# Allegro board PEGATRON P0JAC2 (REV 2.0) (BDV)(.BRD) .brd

Outline 101.61 x 124.8 mm; copper layers: TOP, L2-SIG, L3-GND, L4-SIG, L5-SIG, L6-GND, L7-SIG, BOTTOM. Coordinates in mm from the lower left corner of the outline.

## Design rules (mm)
net group I2C: nets I2C_3_SCL I2C_3_SDA I2C_CAM2_SCL I2C_CAM2_SDA

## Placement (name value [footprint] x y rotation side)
C0706  -  [TX_C0402]  88.72 66.89 270 bottom
C0707  -  [TX_C0402]  87.99 66.89 270 bottom
C0708  -  [TX_C0402]  87.27 66.89 270 bottom
C0710  -  [TX_C0402]  86.94 63.41 180 bottom
C0713  -  [TX_C0402]  86.53 66.89 270 bottom
C0714  -  [TX_C0402]  90.69 87.49 180 bottom
C0715  -  [TX_C0402]  92.33 89.95 0 bottom
C0722  -  [TX_C0402]  85.6 61.5 90 bottom
C0787  -  [TX_C0402]  89.44 66.89 270 bottom
C0901  -  [TX_C0402]  89.02 35.85 0 bottom
C0902  -  [TX_C0402]  86.02 44.08 0 bottom
C0903  -  [TX_C0402]  86.02 44.84 0 bottom
C0904  -  [TX_C0402]  86.02 47.13 0 bottom
C0905  -  [TX_C0402]  86.02 47.89 0 bottom
C0906  -  [TX_C0402]  86.02 40.9 0 bottom
C0907  -  [TX_C0402]  86.02 41.67 0 bottom
C0908  -  [TX_C0402]  86.02 37.86 0 bottom
C0909  -  [TX_C0402]  86.02 38.62 0 bottom
C0910  -  [TX_C0402]  87.29 29.8 90 bottom
C0951  -  [TX_C0402]  85.39 32.09 180 bottom
C0952  -  [TX_C0402]  86.53 32.47 270 bottom
C1001  -  [TX_C0603]  22.09 64.6 180 bottom
C1002  -  [TX_C0402]  23.51 64.53 90 bottom
C1003  -  [TX_C0402_H24]  22.85 65.8 0 bottom
C1004  -  [TX_C0402_H24]  22.85 66.76 0 bottom
C1005  -  [TX_C0402_H24]  23.16 69.55 180 bottom
C1006  -  [TX_C0402_H24]  23.16 70.32 180 bottom
C1007  -  [TX_C0603]  22.03 62.4 180 bottom
C1008  -  [TX_C0603]  22.09 63.49 180 bottom
C1010  -  [TX_C0402]  34.66 68.92 270 bottom
C1020  -  [TX_C0402]  32.63 63.42 90 bottom
C1021  -  [TX_C0402]  33.22 65.46 90 bottom
C1022  -  [TX_C0402]  33.98 65.46 270 bottom
C1023  -  [TX_C0402]  32.48 67.62 270 bottom
C1024  -  [TX_C0402]  33.24 67.62 90 bottom
C1025  -  [TX_C0402]  28.14 60.03 180 bottom
C1026  -  [TX_C0402]  28.14 60.77 180 bottom
C1027  -  [TX_C0402]  22.78 68.41 270 bottom
C1028  -  [TX_C0603]  21.62 68.58 90 bottom
C1029  -  [TX_C0402]  31.58 61.43 0 bottom
C1030  -  [TX_C0603]  31.17 59.97 270 bottom
C1040  -  [TX_C0603]  24.18 61.66 180 bottom
C1044  -  [TX_C0402]  29.33 70.57 90 bottom
C1045  -  [TX_C0402]  28.58 70.57 90 bottom
C1046  -  [TX_C0402]  27.79 70.57 90 bottom
C1047  -  [TX_C0402]  27.03 70.57 90 bottom
C1052  -  [TX_C0402]  28.14 59.29 180 bottom
C1053  -  [TX_C0402]  20.57 62.82 270 bottom
C1060  -  [TX_C0402]  35.43 70.57 90 bottom
C1061  -  [TX_C0402]  33.9 70.57 90 bottom
C1062  -  [TX_C0402]  31.62 70.57 90 bottom
C1063  -  [TX_C0402]  27.84 72.17 90 bottom
C1102  -  [TX_C0402]  25.6 60.89 90 bottom
C1105  -  [TX_C0402]  27.03 60.89 270 bottom
C1106  -  [TX_C0603]  24.78 59.47 180 bottom
C1601  -  [TX_C0402]  72.6 98.41 90 bottom
C1602  -  [TX_C0402]  64.73 86.85 0 bottom
C1603  -  [TX_C0402]  73.36 99.93 90 bottom
C1604  -  [TX_C0402]  59.57 85.38 270 bottom
C1605  -  [TX_C0402]  54.26 86.22 90 bottom
C1606  -  [TX_C0402]  72.6 99.96 90 bottom
C1607  -  [TX_C0402]  49.77 86.49 0 bottom
C1608  -  [TX_C0402]  72.6 96.86 270 bottom
C1609  -  [TX_C0402]  70.49 86.82 0 bottom
C1614  -  [TX_C0402]  57.82 99.65 180 bottom
C1615  -  [TX_C0402]  57.82 98.08 180 bottom
C1616  -  [TX_C0402]  59.11 101.53 270 bottom
C1617  -  [TX_C0402]  68.63 86.85 0 bottom
C1618  -  [TX_C0402]  57.64 101.53 90 bottom
C1619  -  [TX_C0402]  69.35 101.53 270 bottom
C1622  -  [TX_C0402]  73.76 101.53 270 bottom
C1623  -  [TX_C0402]  40.03 97.14 180 bottom
C1624  -  [TX_C0402]  72.29 101.53 270 bottom
C1625  -  [TX_C0402]  40.03 97.9 180 bottom
C1701  -  [TX_C0402]  54.61 101.58 270 bottom
C1702  -  [TX_C0402]  56.85 101.58 270 bottom
C1703  -  [TX_C0402]  48.29 86.4 270 bottom
C1704  -  [TX_C0402]  43.52 101.58 90 bottom
C1705  -  [TX_C0402]  40.03 100.24 180 bottom
C1707  -  [TX_C0402]  40.55 101.58 90 bottom
C1709  -  [TX_C0402]  63.38 82.76 270 bottom
C1710  -  [TX_C0402]  41.28 101.58 90 bottom
C1711  -  [TX_C0402]  47.91 84.36 270 bottom
C1712  -  [TX_C0402]  47.07 84.36 270 bottom
C1713  -  [TX_C0402]  70.09 83.9 270 bottom
C1714  -  [TX_C0402]  60.97 84.95 90 bottom
C1715  -  [TX_C0402]  52.41 86.85 0 bottom
C1716  -  [TX_C0402]  66.3 84.89 90 bottom
C1717  -  [TX_C0402]  52.76 84.74 270 bottom
C1722  -  [TX_C0402]  71.55 101.53 270 bottom
C1723  -  [TX_C0402]  40.03 96.4 180 bottom
C1724  -  [TX_C0402]  40.03 98.64 180 bottom
C1725  -  [TX_C0402]  73.03 101.53 270 bottom
C1900  -  [TX_C0402]  30.96 82.72 270 bottom
C1902  -  [TX_C0402]  32.79 82.72 90 bottom
C1903  -  [TX_C0402]  21.21 88.02 180 bottom
C1904  -  [TX_C0402]  31.73 82.72 270 bottom
C1905  -  [TX_C0402]  21.18 91.85 180 bottom
C1909  -  [TX_C0402]  34.39 82.72 270 bottom
C1911  -  [TX_C0402]  29.41 82.72 270 bottom
C1912  -  [TX_C0402]  21.21 87.26 180 bottom
C1913  -  [TX_C0402]  21.21 88.76 180 bottom
C1914  -  [TX_C0402]  21.21 89.49 180 bottom
C1915  -  [TX_C0402]  21.18 91.09 180 bottom
C1916  -  [TX_C0402]  21.18 90.33 180 bottom
C2011  -  [TX_C0402]  95.83 92.77 0 bottom
C2036  -  [TX_C0402]  25.02 5.04 180 bottom
C2101  -  [TX_C0402]  11.35 111.77 90 bottom
C2102  -  [TX_C0402]  12.87 111.77 90 bottom
C2104  -  [TX_C0402]  15.01 111.26 90 bottom
C2122  -  [TX_C0402]  13.63 111.77 90 bottom
C2124  -  [TX_C0402]  74.35 95.72 180 bottom
C2125  -  [TX_C0402]  80.44 96.47 90 bottom
C2126  -  [TX_C0402]  74.35 98 0 bottom
C2127  -  [TX_C0402]  12.11 111.77 90 bottom
C2128  -  [TX_C0402]  15.75 111.26 90 bottom
C2301  -  [TX_C0402]  83.59 3.82 90 bottom
C2401  -  [TX_C0402]  53.59 81.34 90 bottom
C2600  -  [TX_C0402]  42.26 59.21 270 bottom
C2601  -  [TX_C0402]  42.26 60.73 90 bottom
C2602  -  [TX_C0402]  78.87 65.8 0 bottom
C2603  -  [TX_C0402]  78.87 63.59 0 bottom
C2604  -  [TX_C0402]  65.28 62.19 0 bottom
C2605  -  [TX_C0402]  65.28 61.4 180 bottom
C2606  -  [TX_C0402]  62.74 60.26 90 bottom
C2608  -  [TX_C0402]  65.6 66.48 270 bottom
C2610  -  [TX_C0201]  61.56 58.66 270 bottom
C2611  -  [TX_C0402]  65.25 69.02 0 bottom
C2612  -  [TX_C0402]  65.28 62.95 0 bottom
C2701  -  [TX_C0603_H37]  79.25 74.38 180 bottom
C2706  -  [TX_C0402]  43.13 68.41 180 bottom
C2707  -  [TX_C0402]  43.13 70.62 180 bottom
C2709  -  [TX_C0402]  54.61 61.05 0 bottom
C2710  -  [TX_C0402]  54.61 59.55 0 bottom
C2713  -  [TX_C0402]  54.61 60.28 0 bottom
C2717  -  [TX_C0402]  48.64 60.31 180 bottom
C2718  -  [TX_C0402_H24]  48.64 61.07 180 bottom
C2722  -  [TX_C0402]  51.69 61.07 180 bottom
C2723  -  [TX_C0402]  58.17 60.61 270 bottom
C2724  -  [TX_C0402]  64.87 66.48 270 bottom
C2727  -  [TX_C0402_H24]  63.74 64.45 0 bottom
C2728  -  [TX_C0402]  63.74 63.69 0 bottom
C2729  -  [TX_C0402]  43.13 69.89 180 bottom
C2730  -  [TX_C0402]  48.64 59.55 180 bottom
C2732  -  [TX_C0402]  51.69 60.31 180 bottom
C2733  -  [TX_C0402]  43.13 73.59 180 bottom
C2734  -  [TX_C0402_H26]  63.36 70.16 270 bottom
C2735  -  [TX_C0402]  64.11 70.16 270 bottom
C2736  -  [TX_C0402]  65.64 70.16 270 bottom
C2737  -  [TX_C0402]  64.88 70.16 270 bottom
C2747  -  [TX_C0402]  61.6 61.05 0 bottom
C2748  -  [TX_C0402]  61.6 60.31 0 bottom
C2752  -  [TX_C0402]  50.17 60.31 180 bottom
C2753  -  [TX_C0402]  59.32 60.99 0 bottom
C2754  -  [TX_C0402]  55.73 60.66 270 bottom
C2758  -  [TX_C0402]  60.45 60.64 270 bottom
C2759  -  [TX_C0402]  56.85 61.05 0 bottom
C2760  -  [TX_C0402]  56.85 60.31 0 bottom
C2761  -  [TX_C0402]  56.85 59.57 0 bottom
C2762  -  [TX_C0402]  41.51 67.58 270 bottom
C2763  -  [TX_C0402]  43.49 67.29 270 bottom
C2766  -  [TX_C0402]  64.11 71.69 270 bottom
C2767  -  [TX_C0402]  42.73 74.79 90 bottom
C2768  -  [TX_C0402]  63.36 71.69 270 bottom
C2771  -  [TX_C0402]  41.97 74.79 90 bottom
C2772  -  [TX_C0402]  43.49 74.79 90 bottom
C2773  -  [TX_C0402]  63.36 73.21 90 bottom
C2774  -  [TX_C0402]  63.74 62.95 0 bottom
C2776  -  [TX_C0402]  50.17 61.07 180 bottom
C2777  -  [TX_C0402]  59.32 60.23 0 bottom
C2800  -  [TX_C0402]  63.74 68.26 0 bottom
C2802  -  [TX_C0402]  63.74 69.02 0 bottom
C2803  -  [TX_C0402]  63.74 67.5 0 bottom
C2804  -  [TX_C0402]  63.74 65.97 0 bottom
C2806  -  [TX_C0402]  63.74 66.73 0 bottom
C2807  -  [TX_C0402]  63.74 65.21 0 bottom
C2808  -  [TX_C0402]  44.58 59.65 270 bottom
C2809  -  [TX_C0402]  45.3 59.65 270 bottom
C2810  -  [TX_C0402]  43.1 64.73 180 bottom
C2811  -  [TX_C0402]  43.1 65.47 180 bottom
C2814  -  [TX_C0402]  43.1 63.26 180 bottom
C2815  -  [TX_C0402]  43.1 63.99 180 bottom
C2816  -  [TX_C0402_H26]  50.35 81.34 90 bottom
C2817  -  [TX_C0402]  51.24 81.34 90 bottom
C2818  -  [TX_C0402]  52.13 81.34 90 bottom
C2819  -  [TX_C0402]  58.1 81.34 90 bottom
C2820  -  [TX_C0402]  57.35 81.34 90 bottom
C2821  -  [TX_C0402]  56.63 81.34 90 bottom
C2822  -  [TX_C0402]  59.11 81.34 90 bottom
C2823  -  [TX_C0402]  48.88 81.34 90 bottom
C2824  -  [TX_C0402]  47.99 81.34 90 bottom
C2825  -  [TX_C0402]  43.13 72.86 180 bottom
C3001  -  [TX_C0402]  78.82 68.95 0 bottom
C3002  -  [TX_C0402]  69.93 62.54 90 bottom
C3003  -  [TX_C0201]  70.56 62.54 90 bottom
C3004  -  [TX_C0201]  74.55 62.85 0 bottom
C3005  -  [TX_C0201]  76.07 74.03 0 bottom
C3006  -  [TX_C0201]  73.51 62.85 180 bottom
C3007  -  [TX_C0201]  71.12 74.48 90 bottom
C3008  -  [TX_C0201]  66.52 68.18 180 bottom
C3009  -  [TX_C0201]  78.25 67.26 90 bottom
C3010  -  [TX_C0201]  67.29 68.27 90 bottom
C3011  -  [TX_C0201]  78.49 66.42 0 bottom
C3101  -  [TX_C0402]  40.01 99.45 180 bottom
C3311  -  [TX_C0402]  16.59 74.72 0 bottom
C3316  -  [TX_C0402]  80.65 90.36 270 bottom
C3317  -  [TX_C0402]  79.76 86.37 90 bottom
C3318  -  [TX_C0402]  79.4 80.78 90 bottom
C3319  -  [TX_C0402]  76.96 77.99 90 bottom
C3801  -  [TX_C0402]  84.23 89.06 180 bottom
C5101  -  [TX_C0402]  31.06 9.46 0 bottom
C5102  -  [TX_C0402]  25.4 10.75 270 bottom
C5103  -  [TX_C0402]  24.66 10.75 270 bottom
C5209  -  [TX_C0402]  72.16 48.9 180 bottom
C5210  -  [TX_C0402_H28]  73.2 46.87 270 bottom
C5211  -  [TX_C0402_H26]  89.35 59.01 90 bottom
C5212  -  [TX_C0402_H26]  89.35 57.49 270 bottom
C5214  -  [TX_C0402_H28]  73.94 46.87 270 bottom
C5215  -  [TX_C0402]  73.81 53.53 0 bottom
C5216  -  [TX_C0402]  89.35 55.91 90 bottom
C5217  -  [TX_C0402]  88.61 55.91 90 bottom
C5401  -  [TX_C0402_H26]  16.79 90.89 0 bottom
C5402  -  [TX_C0402]  16.79 90.08 0 bottom
C5403  -  [TX_C0402]  16.79 89.27 0 bottom
C5404  -  [TX_C0402]  1.88 81.01 90 bottom
C5405  -  [TX_C0402]  2.36 91.32 180 bottom
C5406  -  [TX_C0402_H26]  2.36 89.72 180 bottom
C5407  -  [TX_C0402]  2.36 88.12 0 bottom
C5410  -  [TX_C0402]  1.91 85.86 90 bottom
C5411  -  [TX_C0402]  17.15 77.48 0 bottom
C5412  -  [TX_C0402]  2.36 90.51 180 bottom
C5413  -  [TX_C0402]  2.36 92.14 180 bottom
C5414  -  [TX_C0402]  8.71 72.35 180 bottom
C5415  -  [TX_C0402]  8.77 74.26 270 bottom
C5416  -  [TX_C0402]  8.03 74.26 270 bottom
C5417  -  [TX_C0402]  5.78 74.26 270 bottom
C5810  -  [TX_C0402]  28.65 101.38 180 bottom
C5811  -  [TX_C0402]  28.68 99.35 180 bottom
C5812  -  [TX_C0402]  28.68 97.88 180 bottom
C5813  -  [TX_C0402]  88.57 111.77 90 bottom
C5819  -  [TX_C0402]  71.74 114.63 0 bottom
C5820  -  [TX_C0402]  69.55 113.57 270 bottom
C5841  -  [TX_C0402]  89.31 111.77 90 bottom
C5866  -  [TX_C0402]  89.31 108.52 270 bottom
C5867  -  [TX_C0402]  88.57 108.52 270 bottom
C5878  -  [TX_C0402]  92.51 67.24 0 bottom
C7001  -  [TX_C0402]  28.85 50.35 90 bottom
C7002  -  [TX_C0402]  34.39 49.08 90 bottom
C7003  -  [TX_C0402]  29.61 50.35 90 bottom
C7010  -  [TX_C0402]  37.36 47.41 90 bottom
C7011  -  [TX_C0402]  37.36 45.86 270 bottom
C7103  -  [TX_C0402_H26]  76.7 20.41 270 bottom
C7104  -  [TX_C0402]  64.43 20 90 bottom
C7105  -  [TX_C0402]  64.43 18.47 270 bottom
C7106  -  [TX_C0402]  72.18 22.95 0 bottom
C7108  -  [TX_C0402]  72 13.14 0 bottom
C7109  -  [TX_C0402]  67.43 13.14 0 bottom
C7110  -  [TX_C0402]  74.86 19.74 90 bottom
C7111  -  [TX_C0402]  65.17 16.19 180 bottom
C7112  -  [TX_C0402]  74.14 19.74 90 bottom
C7117  -  [TX_C0402]  54.17 19.57 90 bottom
C7118  -  [TX_C0402]  54.96 19.57 90 bottom
C7119  -  [TX_C0402_H24]  53.44 19.57 270 bottom
C7120  -  [TX_C0402]  52.65 19.57 270 bottom
C7125  -  [TX_C0402]  65 25.71 270 bottom
C7126  -  [TX_C0603_H39]  67.03 29.09 180 bottom
C7146  -  [TX_C0402]  69.43 23.41 90 bottom
C7147  -  [TX_C0402]  67.22 23.41 90 bottom
C7148  -  [TX_C0402]  67.95 23.41 90 bottom
C7149  -  [TX_C0402]  68.69 23.41 90 bottom
C7150  -  [TX_C0402]  41.17 24.47 180 bottom
C7166  -  [TX_C0402]  70.48 13.14 180 bottom
C7187  -  [TX_C0402]  68.95 13.14 0 bottom
C7312  -  [TX_C0402]  47.85 4.02 90 bottom
C7313  -  [TX_C0402]  47.98 9.11 90 bottom
C7316  -  [TX_C0603_H37]  55.25 13.42 0 bottom
C7317  -  [TX_C0402_H24]  53.29 12.48 180 bottom
C7318  -  [TX_C0402_H24]  47.22 9.11 90 bottom
C7321  -  [TX_C0402]  67.22 4.15 0 bottom
C7322  -  [TX_C0402]  67.22 3.37 0 bottom
C7323  -  [TX_C0402]  67.49 5.65 0 bottom
C7324  -  [TX_C0402]  67.22 4.92 0 bottom
C7330  -  [TX_C0402]  88.32 7.17 270 bottom
C7331  -  [TX_C0402]  87.61 5.83 0 bottom
C7341  -  [TX_C0402]  62.99 4.53 90 bottom
C7342  -  [TX_C0402]  62.99 3.01 270 bottom
C7350  -  [TX_C0402]  87.47 14.11 90 bottom
C7351  -  [TX_C0402]  88.24 14.11 90 bottom
C7352  -  [TX_C0402]  86.71 14.11 90 bottom
C7353  -  [TX_C0402]  87.37 11.01 90 bottom
C7354  -  [TX_C0402]  88.13 11.01 90 bottom
C7355  -  [TX_C0402]  86.61 11.01 90 bottom
C7356  -  [TX_C0402]  49.98 13.12 270 bottom
C7357  -  [TX_C0402]  49.22 13.12 270 bottom
C7358  -  [TX_C0402_H24]  50.74 13.12 90 bottom
C7359  -  [TX_C0402]  43.28 15.23 180 bottom
C7364  -  [TX_C0402]  54.97 12.48 0 bottom
C7377  -  [TX_C0402]  62.69 9.12 90 bottom
C7385  -  [TX_C0603]  52.99 13.42 180 bottom
C7388  -  [TX_C0402]  84.15 5.83 0 bottom
C7389  -  [TX_C0402]  84.56 7.22 270 bottom
C7390  -  [TX_C0402]  79.02 9.11 90 bottom
C7391  -  [TX_C0402]  78.84 5.83 180 bottom
C8001  -  [TX_C0402_H24]  73.36 9.5 0 bottom
C8002  -  [TX_C0402]  71.91 9.11 90 bottom
C8003  -  [TX_C0402]  68.71 6.77 0 bottom
C8004  -  [TX_C0402]  71.15 9.11 90 bottom
C8005  -  [TX_C0402]  73.36 8.77 0 bottom
C8100  -  [TX_C0402]  74.55 44.54 90 bottom
C8101  -  [TX_C0603_H39]  73.78 36.1 270 bottom
C8102  -  [TX_C0402]  80.93 43.9 270 bottom
C8105  -  [TX_C0603_H39]  75.26 46.57 270 bottom
C8106  -  [TX_C0402]  73.62 42.71 180 bottom
C8107  -  [TX_C0402]  80.19 43.9 270 bottom
C8108  -  [TX_C0603_H39]  76.38 46.57 270 bottom
C8109  -  [TX_C0603_H37]  29.9 43.82 180 bottom
C8110  -  [TX_C0402]  34.82 42.68 0 bottom
C8111  -  [TX_C0603_H39]  34.92 45.27 90 bottom
C8112  -  [TX_C0603_H39]  33.76 45.3 90 bottom
C8113  -  [TX_C0402]  36.24 45.45 0 bottom
C8114  -  [TX_C0402]  29.59 42.91 180 bottom
C8115  -  [TX_C0402]  80.04 84.2 0 bottom
C8116  -  [TX_C0402]  74.47 83.8 270 bottom
C8201  -  [TX_C0603]  52.97 37.83 270 bottom
C8202  -  [TX_C0603]  58.61 39.51 0 bottom
C8203  -  [TX_C0603]  51.87 37.83 270 bottom
C8204  -  [TX_C0603]  56.5 41.12 0 bottom
C8205  -  [TX_C0603]  56.5 40.02 0 bottom
C8206  -  [TX_C0603]  63.58 37.63 270 bottom
C8207  -  [TX_C0603]  64.69 37.63 270 bottom
C8208  -  [TX_C0603]  61.37 39.81 0 bottom
C8209  -  [TX_C0603]  61.37 40.9 0 bottom
C8210  -  [TX_C0603]  63.91 35.39 90 bottom
C8211  -  [TX_C0603_H39]  61.7 49.03 180 bottom
C8212  -  [TX_C0603_H39]  61.7 50.15 180 bottom
C8213  -  [TX_C0603_H39]  65.4 51.55 90 bottom
C8214  -  [TX_C0603_H39]  69.44 45.83 0 bottom
C8215  -  [TX_C0603_H39]  69.44 50.3 0 bottom
C8216  -  [TX_C0603_H39]  69.44 48.07 0 bottom
C8217  -  [TX_C0603_H39]  69.79 36.76 0 bottom
C8218  -  [TX_C0603_H39]  69.79 39.01 0 bottom
C8219  -  [TX_C0201]  65.28 42.96 180 bottom
C8220  -  [TX_C0603_H39]  59.51 46.83 0 bottom
C8221  -  [TX_C0603_H39]  59.51 47.94 0 bottom
C8222  -  [TX_C0603_H39]  52.91 52.02 90 bottom
C8223  -  [TX_C0603_H39]  49.38 52.02 90 bottom
C8224  -  [TX_C0603_H39]  48.51 48.09 180 bottom
C8225  -  [TX_C0603_H39]  48.51 49.23 180 bottom
C8226  -  [TX_C0603_H39]  48.51 45.87 180 bottom
C8227  -  [TX_C0603_H39]  48.51 46.97 180 bottom
C8228  -  [TX_C0201]  47.16 49.32 90 bottom
C8229  -  [TX_C0603]  63.42 32.65 270 bottom
C8230  -  [TX_C0603_H39]  71.01 29.57 270 bottom
C8231  -  [TX_C0603_H39]  69.87 29.57 270 bottom
C8232  -  [TX_C0603_H39]  68.73 29.57 270 bottom
C8233  -  [TX_C0603_H39]  72.16 29.57 270 bottom
C8235  -  [TX_C0603]  64.54 32.65 270 bottom
C8237  -  [TX_C0603_H39]  71.42 33.29 0 bottom
C8239  -  [TX_C0603]  56.36 30.26 180 bottom
C8241  -  [TX_C0603_H39]  51.17 27.39 180 bottom
C8242  -  [TX_C0603_H39]  51.18 26.25 180 bottom
C8244  -  [TX_C0603_H39]  51.18 25.08 180 bottom
C8245  -  [TX_C0603_H39]  51.18 23.96 180 bottom
C8246  -  [TX_C0603]  53.09 35.54 90 bottom
C8248  -  [TX_C0603_H39]  46.48 34.57 180 bottom
C8249  -  [TX_C0603_H39]  46.48 35.67 180 bottom
C8250  -  [TX_C0603_H39]  47.42 37.3 90 bottom
C8251  -  [TX_C0603]  52.91 32.06 270 bottom
C8253  -  [TX_C0603_H39]  46.53 29.8 90 bottom
C8254  -  [TX_C0603_H39]  47.64 29.8 90 bottom
C8255  -  [TX_C0603_H39]  45.41 27.64 270 bottom
C8256  -  [TX_C0603_H39]  47.64 27.64 270 bottom
C8257  -  [TX_C0603_H39]  49.4 27.01 270 bottom
C8258  -  [TX_C0603]  65.28 27.75 270 bottom
C8260  -  [TX_C0603_H37]  61.06 23.94 180 bottom
C8261  -  [TX_C0603_H37]  61.36 26.15 180 bottom
C8262  -  [TX_C0603_H37]  62.38 22.16 0 bottom
C8263  -  [TX_C0603_H37]  61.36 27.29 180 bottom
C8264  -  [TX_C0603_H37]  61.36 28.43 180 bottom
C8265  -  [TX_C0603_H37]  61.06 25.04 180 bottom
C8266  -  [TX_C0402]  62.88 51.06 180 bottom
C8267  -  [TX_C0402]  62.88 51.83 180 bottom
C8268  -  [TX_C0402]  65.96 53.02 180 bottom
C8269  -  [TX_C0402]  54.81 52 90 bottom
C8270  -  [TX_C0402]  55.6 52 90 bottom
C8271  -  [TX_C0402]  62.61 53.22 0 bottom
C8273  -  [TX_C0603_H39]  71.42 34.41 0 bottom
C8274  -  [TX_C0603_H39]  61.7 46.8 180 bottom
C8275  -  [TX_C0603_H39]  61.7 47.91 180 bottom
C8276  -  [TX_C0603_H39]  69.44 44.71 0 bottom
C8277  -  [TX_C0603_H39]  64.26 51.55 90 bottom
C8278  -  [TX_C0603_H39]  69.44 46.95 0 bottom
C8279  -  [TX_C0603_H39]  69.44 49.18 0 bottom
C8280  -  [TX_C0603_H39]  69.79 35.66 0 bottom
C8281  -  [TX_C0603_H39]  69.79 37.88 0 bottom
C8282  -  [TX_C0603_H39]  59.51 49.04 0 bottom
C8283  -  [TX_C0603_H39]  59.53 50.16 0 bottom
C8284  -  [TX_C0603_H39]  50.5 52.02 90 bottom
C8285  -  [TX_C0603_H39]  51.61 52.02 90 bottom
C8286  -  [TX_C0603_H39]  48.25 52.02 90 bottom
C8287  -  [TX_C0603_H39]  48.51 50.38 180 bottom
C8288  -  [TX_C0603_H39]  48.51 43.65 180 bottom
C8289  -  [TX_C0603_H39]  48.51 44.76 180 bottom
C8290  -  [TX_C0402]  50.03 20.02 180 bottom
C8291  -  [TX_C0402]  48.63 19.64 90 bottom
C8299  -  [TX_C0402]  71.27 35.85 270 bottom
C8301  -  [TX_C0201]  49.3 33.08 180 bottom
C8302  -  [TX_C0603_H39]  46.98 32.6 90 bottom
C8303  -  [TX_C0603_H39]  48.13 32.6 90 bottom
C8304  -  [TX_C0603_H37]  69.62 40.78 270 bottom
C8305  -  [TX_C0603_H37]  59.39 24.95 270 bottom
C8306  -  [TX_C0201]  42.11 38.11 90 bottom
C8307  -  [TX_C0603]  71.85 25.85 90 bottom
C8308  -  [TX_C0402]  70.94 25.54 90 bottom
C8309  -  [TX_C0402]  71.75 27.29 0 bottom
C8310  -  [TX_C0201_H14]  43.59 40.55 90 bottom
C8311  -  [TX_C0603_H37]  47.01 41.21 270 bottom
C8312  -  [TX_C0603_H37]  45.71 41.18 270 bottom
C8313  -  [TX_C0603_H37]  44.47 41.21 270 bottom
C8314  -  [TX_C0402]  47.09 39.79 0 bottom
C8315  -  [TX_C0402_H26]  44.83 38.01 180 bottom
C8316  -  [TX_C0201_H14]  48.55 36.56 180 bottom
C8317  -  [TX_C0402]  43.63 37.55 270 bottom
C8318  -  [TX_C0603_H37]  43.2 44.15 270 bottom
C8319  -  [TX_C0402_H24]  51.77 33.46 270 bottom
C8320  -  [TX_C0603_H39]  57.68 23.2 0 bottom
C8321  -  [TX_C0603_H39]  57.68 24.32 0 bottom
C8322  -  [TX_C0603_H39]  54.35 25.51 180 bottom
C8323  -  [TX_C0603_H39]  57.68 22.08 0 bottom
C8324  -  [TX_C0603_H39]  54.35 23.22 180 bottom
C8325  -  [TX_C0603_H39]  54.35 24.37 180 bottom
C8326  -  [TX_C0603_H39]  57.68 25.43 0 bottom
C8327  -  [TX_C0603]  59.94 29.58 180 bottom
C8329  -  [TX_C0402]  58.31 19.57 90 bottom
C8330  -  [TX_C0402]  64.97 23.3 270 bottom
C8331  -  [TX_C0402_H26]  74.67 24.9 270 bottom
C8332  -  [TX_C0402]  77.12 28.71 0 bottom
C8333  -  [TX_C0402]  78.84 27.62 0 bottom
C8334  -  [TX_C0402]  80.41 25.31 0 bottom
C8335  -  [TX_C0402]  36.58 65.47 90 bottom
C8336  -  [TX_C0402]  34.27 60.56 90 bottom
C8341  -  [TX_C0402]  74.14 29.78 180 bottom
C8342  -  [TX_C0201_H14]  64.19 30.79 270 bottom
C8343  -  [TX_C0402]  73.67 34.09 270 bottom
C8344  -  [TX_C0201]  76.78 32.32 270 bottom
C8345  -  [TX_C0402]  73.71 32.55 270 bottom
C8346  -  [TX_C0201]  74.65 31.15 90 bottom
C8348  -  [TX_C0402]  56.84 18.02 270 bottom
C8349  -  [TX_C0402]  80.82 23.73 90 bottom
C8367  -  [TX_C0402]  55.83 25.36 90 bottom
C8401  -  [TX_C0201_H14]  58.14 20.94 270 bottom
C8402  -  [TX_C0402]  49.3 23.22 90 bottom
C8405  -  [TX_C0402]  37.11 41.89 90 bottom
C8406  -  [TX_C0402]  43.19 42 90 bottom
C8407  -  [TX_C0402]  30.46 51.95 180 bottom
C8408  -  [TX_C0402]  35.68 50.76 270 bottom
C8409  -  [TX_C0201_H14]  63.63 30.79 270 bottom
C8410  -  [TX_C0201]  59.77 20.94 270 bottom
C8411  -  [TX_C0201]  41.58 38.11 90 bottom
C8412  -  [TX_C0402]  36.57 50.63 270 bottom
C8800  -  [TX_C0402_H26]  38.86 23 180 bottom
C8801  -  [TX_C0805]  38.75 21.14 270 bottom
C8802  -  [TX_C0402]  38.07 25.13 180 bottom
C8803  -  [TX_C0402]  37.05 21.09 0 bottom
C8804  -  [TX_C0805]  36.46 19.92 180 bottom
C8805  -  [TX_C0805]  36.46 18.27 180 bottom
C8806  -  [TX_C0402]  37.05 21.83 0 bottom
C8807  -  [TX_C0402]  38.91 36.23 0 bottom
C8808  -  [TX_C0402]  38.91 35.49 0 bottom
C8809  -  [TX_C0603_H39]  39.11 34.53 0 bottom
C8810  -  [TX_C0603_H39]  39.11 33.38 0 bottom
C8811  -  [TX_C0402]  30.93 26.02 180 bottom
C8812  -  [TX_C0603_H37]  31.16 26.93 180 bottom
C8814  -  [TX_C0603]  69.06 9.33 0 bottom
C8816  -  [TX_C0402]  31.69 13.27 270 bottom
C8817  -  [TX_C0402]  30.56 13.62 0 bottom
C8818  -  [TX_C0402]  31.24 16.93 180 bottom
C8905  -  [TX_C0402]  29.63 31.4 90 bottom
C8906  -  [TX_C0402]  25.32 40.22 270 bottom
C8907  -  [TX_C0402]  30.02 32.51 180 bottom
C8911  -  [TX_C0402]  25.73 44.28 90 bottom
C8912  -  [TX_C0402]  30.02 33.23 180 bottom
C8913  -  [TX_C0402]  30.03 35.42 180 bottom
C8916  -  [TX_C0402]  34.44 35.81 90 bottom
C8917  -  [TX_C0402]  33.29 37.07 0 bottom
C8918  -  [TX_C0402]  33.29 37.86 0 bottom
C8919  -  [TX_C0402]  34.82 37.45 180 bottom
C9000  -  [TX_C0402]  40.24 14.23 0 bottom
C9001  -  [TX_C0402_H24]  40.24 14.97 0 bottom
C9002  -  [TX_C0402]  42.72 21.5 180 bottom
C9003  -  [TX_C0402]  41.17 23.73 0 bottom
C9004  -  [TX_C0402_H24]  43.71 18.12 270 bottom
C9005  -  [TX_C0805_H49]  43.66 4.99 0 bottom
C9006  -  [TX_C0603_H37]  47.18 5.34 0 bottom
C9007  -  [TX_C0402]  41.17 25.94 180 bottom
C9008  -  [TX_C0402]  42.85 27.26 90 bottom
C9009  -  [TX_C0603_H37]  46.91 18.07 270 bottom
C9010  -  [TX_C0805_H49]  43.66 3.34 0 bottom
CE5201  -  [TX_C3216_H47]  88.77 51.7 90 bottom
CE5202  -  [TX_C3216_H47]  86.86 51.7 90 bottom
CE8100  -  [TX_C3216_H47]  77.85 49.39 270 bottom
CE8101  -  [TX_C3216_H47]  79.73 48.19 270 bottom
CE8102  -  [TX_C3528_SANYO_H47]  31.85 40.06 180 bottom
CON0700  -  [TX_MICRO_SD_8P_11HOLD]  93.63 75.56 270 bottom
CON0901  -  [T_NB_HDMI_19P_16_4HL_RA_LF2]  97.13 40.24 90 top
CON1102  -  [TX_WTOB_4P_31_2H_ENT]  34.37 2.36 180 bottom
CON2002  -  [TX_FPC_18P_20_2H_RA_B]  1.65 64.6 90 bottom
CON2003  -  [TX_FPC_6P_20_2HOLD_ACES]  20.55 3.03 180 bottom
CON2101  -  [TX_FPC_21P_24_2H_RA_SUNG]  6.55 119.79 180 bottom
CON3301  -  [TX_FPC_12P_20_2HOLD_RA_PTWO]  13.87 70.95 180 bottom
CON3800  -  [TX_BTOB_60P_16_4H_F_PANA]  86.6 92.87 270 bottom
CON5101  -  [TX_WTOB_9P_79_2HOLD_ACE]  18.98 24.5 90 bottom
CON5201  -  [TX_USB_5P_4HOLD_RA_ACON]  97.76 56.97 90 top
CON7305  -  [TX_FPC_39P_24_2HOLD_RA_HSR]  55.36 3.32 180 bottom
CON8001  -  [TX_WTOB_4P_49_2HOLD_RA_H88]  73.51 1.9 180 bottom
CON8902  -  [TX_WTOB_6P_79_2HOLD_ACE]  18.98 47.15 90 bottom
D0700  -  [TX_ESD_2P_33_39X24_H20]  90.73 85.05 180 bottom
D0701  -  [TX_ESD_2P_33_39X24_H20]  90.73 84.21 180 bottom
D0702  -  [TX_ESD_2P_33_39X24_H20]  90.68 89.11 180 bottom
D0703  -  [TX_ESD_2P_33_39X24_H20]  90.68 88.27 180 bottom
D0704  -  [TX_ESD_2P_33_39X24_H20]  90.73 85.89 180 bottom
D0705  -  [TX_ESD_2P_33_39X24_H20]  90.7 86.7 180 bottom
D0706  -  [TX_ESD_2P_33_39X24_H20]  90.68 89.95 180 bottom
D0905  -  [TX_SOT323]  85.85 34.76 270 bottom
D1101  -  [TX_ESD_2P_33_39X24_H20]  32.41 5.66 180 bottom
D1102  -  [TX_ESD_2P_33_39X24_H20]  34.04 5.66 0 bottom
D1103  -  [TX_ESD_2P_33_39X24_H20]  35.65 5.65 180 bottom
D1104  -  [TX_ESD_2P_33_39X24_H20]  37.28 5.65 0 bottom
D2003  -  [TX_DIODE_2P_39X24_INFINEON]  96.27 95.29 90 bottom
D2701  -  [TX_SOT323]  79.17 72.3 270 bottom
D5102  -  [TX_SOT323]  25.93 8.82 180 bottom
D5103  -  [TX_DIODE_2P_39X24_INFINEON]  29.77 17.05 0 bottom
D5104  -  [TX_SOT323]  28.91 2.68 180 bottom
D8101  -  [TX_SOT323]  71.65 46.97 90 bottom
D8201  -  [TX_DFN1006_2]  62.81 30.92 270 bottom
D9000  -  [TX_POWERDI123]  42.36 18.3 90 bottom
D9001  -  [TX_POWERDI123]  45.74 7.04 180 bottom
F0921  -  [TX_FUSE_2P_39X20_H14]  87.98 36.6 0 bottom
H7901  -  [HOLE_O118X106DO118X106N]  95.11 101.25 90 top
H7903  -  [HOLE_C106D106N]  92.51 48.5 0 top
H7906  -  [HOLE_C106D106N]  14.09 121.95 0 top
H7907  -  [HOLE_CRT262X204D79]  93.6 32.74 0 top
H7910  -  [HH_H_RC262X258D79N_P2_V4]  14.09 117.45 0 top
H7911  -  [HH_H_R276X277D79N_M2_P2_V4]  95.1 106.4 0 top
J3101  -  [TX_FPC_CON_34P_31_2HD_T]  63.29 108.67 180 top
JP1601  -  [2MM_OPEN_5MIL_M1M2]  44.22 83.27 180 bottom
JP1602  -  [1MM_OPEN_5MIL_M1M2]  44.32 33.66 180 bottom
JP8100  -  [HH_PWR_FB_SHORT_PT]  79.78 47.58 90 bottom
JP8101  -  [1MM_OPEN_5MIL_M1M2]  72.88 39.07 90 bottom
JP8102  -  [1MM_OPEN_5MIL_M1M2]  74.96 48.7 270 bottom
JP8201  -  [HH_PWR_FB_SHORT_PT]  72.16 29.85 270 bottom
JP8202  -  [HH_PWR_FB_SHORT_PT]  71.09 34.45 0 bottom
JP8203  -  [HH_PWR_FB_SHORT_PT]  51.43 23.96 180 bottom
JP8204  -  [HH_PWR_FB_SHORT_PT]  46.64 34.53 0 bottom
JP8205  -  [HH_PWR_FB_SHORT_PT]  46.53 29.63 270 bottom
JP8206  -  [HH_PWR_FB_SHORT_PT]  62.1 22.26 180 bottom
JP8207  -  [HH_PWR_FB_SHORT_PT]  70.1 50.86 270 bottom
JP8301  -  [HH_PWR_FB_SHORT_PT]  46.98 31.45 270 bottom
JP8302  -  [HH_PWR_FB_SHORT_PT]  57.04 21.5 90 bottom
JP8303  -  [HH_PWR_FB_SHORT_PT]  73.53 25.41 180 bottom
JP8304  -  [HH_PWR_FB_SHORT_PT]  80.08 24.98 270 bottom
JP8305  -  [HH_PWR_FB_SHORT_PT]  36.98 65.06 0 bottom
JP8306  -  [1MM_OPEN_5MIL_M1M2]  38.68 73.72 180 bottom
JP8307  -  [1MM_OPEN_5MIL_M1M2]  40.54 73.72 180 bottom
JP8402  -  [HH_PWR_FB_SHORT_PT]  37.14 41.08 270 bottom
JP8800  -  [2MM_OPEN_5MIL_M1M2]  31.01 29.07 180 bottom
JP8900  -  [HH_PWR_FB_SHORT_PT]  29.59 48.45 90 bottom
JP8901  -  [HH_PWR_FB_SHORT_PT]  28.7 47.69 270 bottom
JP9000  -  [1MM_OPEN_5MIL_M1M2]  46.5 2.96 90 bottom
JP9001  -  [HH_PWR_FB_SHORT_PT]  46.88 5.32 180 bottom
L0900  -  [TX_CHOKE_4P_49X39]  87.92 44.46 0 bottom
L0901  -  [TX_CHOKE_4P_49X39]  87.92 47.51 0 bottom
L0902  -  [TX_CHOKE_4P_49X39]  87.92 41.31 0 bottom
L0903  -  [TX_CHOKE_4P_49X39]  87.92 38.21 0 bottom
L2102  -  [TX_CHOKE_4P_49X39]  22.57 98.36 90 bottom
L2104  -  [TX_CHOKE_4P_49X39]  21.36 98.36 90 bottom
L3001  -  [TX_L0402_H24]  68.3 62.26 0 bottom
L3002  -  [TX_L0402_H24]  68.3 62.97 0 bottom
L3003  -  [TX_L0402_H24]  70.05 74.11 180 bottom
L5201  -  [TX_CHOKE_4P_49X39]  87.88 58.25 180 bottom
L5202  -  [TX_L0805_H43]  86.34 55.58 0 bottom
L7102  -  [TX_L0603_H26]  75.77 20.05 270 bottom
L7111  -  [TX_L1008_MURA]  75.05 22.56 0 bottom
L7303  -  [TX_L0402_H24]  52.5 14.41 0 bottom
L7304  -  [TX_L0402_H24]  45.69 9.11 270 bottom
L7305  -  [TX_L0402_H24]  46.45 9.11 270 bottom
L7306  -  [TX_L0402_H24]  65.33 8.95 180 bottom
L7350  -  [TX_L0402_H24]  63.81 8.95 180 bottom
L8001  -  [TX_L0805_H43]  69.34 7.97 180 bottom
L8100  -  [TX_INDUCTOR_2P_213X205_H59]  77.48 38.06 0 bottom
L8101  -  [TX_INDUCTOR_2P_98X79_TAIYO]  31.7 45.63 0 bottom
L8201  -  [TX_INDUCTOR_2P_98X79_TAIYO]  62.54 43.27 270 bottom
L8202  -  [TX_INDUCTOR_2P_98X79_TAIYO]  60.25 43.27 270 bottom
L8203  -  [TX_INDUCTOR_2P_98X79_TAIYO]  66 40.99 180 bottom
L8204  -  [TX_INDUCTOR_2P_98X79_TAIYO]  66.92 38.74 180 bottom
L8205  -  [TX_INDUCTOR_2P_98X79_TAIYO]  66.82 36.27 180 bottom
L8206  -  [TX_INDUCTOR_2P_98X79_TAIYO]  55.73 43.24 270 bottom
L8207  -  [TX_INDUCTOR_2P_98X79_TAIYO]  58.01 43.24 270 bottom
L8208  -  [TX_INDUCTOR_2P_98X79_TAIYO]  52.86 43.24 270 bottom
L8209  -  [TX_INDUCTOR_2P_98X79_TAIYO]  51 40.27 0 bottom
L8210  -  [TX_INDUCTOR_2P_98X79_TAIYO]  49.78 37.96 0 bottom
L8211  -  [TX_INDUCTOR_2P_98X79_TAIYO]  67.11 31.79 180 bottom
L8212  -  [TX_INDUCTOR_2P_98X79_TAIYO]  67.13 34.03 180 bottom
L8213  -  [TX_INDUCTOR_2P_98X79_TAIYO]  55.17 27.85 0 bottom
L8214  -  [TX_INDUCTOR_2P_98X79_TAIYO]  50.57 35.42 180 bottom
L8215  -  [TX_INDUCTOR_2P_98X79_TAIYO]  50.75 31.58 180 bottom
L8216  -  [TX_INDUCTOR_2P_98X79_TAIYO]  63.6 28.18 270 bottom
L8301  -  [TX_INDUCTOR_2P_98X79_TAIYO]  58.8 27.82 180 bottom
L8801  -  [TX_INDUCTOR_2P_213X205_H59]  36.57 30.03 180 bottom
L9000  -  [TX_L1008_TAIYO_H47]  45.18 20 90 bottom
LX7324  -  [TX_CHOKE_4P_49X39]  64.56 6.56 180 bottom
LX7325  -  [TX_CHOKE_4P_49X39]  64.56 3.82 180 bottom
LX7326  -  [TX_CHOKE_4P_49X39]  64.56 7.96 180 bottom
LX7327  -  [TX_CHOKE_4P_49X39]  64.56 5.22 180 bottom
LX7328  -  [TX_CHOKE_4P_49X39]  64.59 2.45 180 bottom
NOREF  -  [unnamed]  96.42 43.29 0 top
NOREF#2  -  [unnamed]  -81.77 -17.72 90 top
NOREF#3  -  [#2]  49.53 84.99 0 top
NOREF#4  -  [#2]  57.34 86.71 0 top
NOREF#5  -  [#2]  6.33 132.78 0 top
NOREF#6  -  [unnamed#3]  -67.8 131.72 90 top
NOREF#7  -  [#2]  -31.01 130.45 0 top
NOREF#8  -  [unnamed]  -81.77 131.72 90 top
NOREF#9  -  [unnamed#3]  84.58 2.75 0 top
NOREF#10  -  [unnamed#3]  29.11 111.64 0 top
NOREF#11  -  [unnamed]  96.53 -17.72 270 top
NOREF#12  -  [unnamed#3]  -72.88 -17.72 90 top
NOREF#13  -  [#2]  49 -16.45 0 top
NOREF#14  -  [unnamed#3]  82.56 131.72 270 top
NOREF#15  -  [unnamed]  96.53 131.72 270 top
NOREF#16  -  [unnamed#3]  22.73 8.47 0 top
NOREF#17  -  [unnamed#3]  87.64 -17.72 270 top
NOREF#18  -  [unnamed]  96.41 37.19 0 top
NOREF#19  -  [#2]  -57.35 -45.63 0 top
NOREF#20  -  [unnamed#3]  81.53 2.75 180 bottom
NOREF#21  -  [unnamed#3]  82.56 -17.72 90 bottom
NOREF#22  -  [#2]  -31.01 130.45 180 bottom
NOREF#23  -  [#2]  49 -16.45 180 bottom
NOREF#24  -  [unnamed#3]  77.48 131.72 90 bottom
NOREF#25  -  [unnamed#3]  29.11 111.64 180 bottom
NOREF#26  -  [unnamed#3]  -62.72 131.72 270 bottom
NOREF#27  -  [unnamed#3]  22.73 10.25 180 bottom
NOREF#28  -  [unnamed#3]  -67.8 -17.72 270 bottom
NOREF#29  -  [#2]  6.33 132.78 180 bottom
Q0703  -  [TX_SOT23_2D4_H44]  87.88 61.48 90 bottom
Q0704  -  [TX_SC70_S6_H47]  85.62 58.15 180 bottom
Q0901  -  [TX_SC70_S6_H47]  86.61 27.9 270 bottom
Q0902  -  [TX_VMT3_3P_ROHM]  88.89 34.44 180 bottom
Q0903  -  [TX_VMT3_3P_ROHM]  88.89 32.17 180 bottom
Q2001  -  [TX_SC70_S6_H47]  40.29 5.47 270 bottom
Q2025  -  [TX_VMT3_3P_ROHM]  25.39 3.9 270 bottom
Q2644  -  [TX_SC70_S6_H47]  87.15 64.91 270 bottom
Q2650  -  [TX_SC70_S6_H47]  38.48 68.23 180 bottom
Q2655  -  [TX_VMT3_3P_ROHM]  24.21 72.57 180 bottom
Q2660  -  [TX_SC70_S6_H47]  34.47 8.72 90 bottom
Q3004  -  [TX_SC70_S6_H47]  75.49 79 180 bottom
Q3006  -  [TX_SC70_S6_H47]  78.92 76.13 270 bottom
Q3007  -  [TX_VMT3_3P_ROHM]  37.16 71.05 0 bottom
Q3008  -  [TX_SC70_S6_H47]  74.73 60.49 90 bottom
Q3009  -  [TX_SC70_S6_H47]  70.23 60.06 270 bottom
Q3101  -  [TX_SC70_S6_H47]  36.7 100.01 180 bottom
Q3301  -  [TX_VMT3_3P_ROHM]  80.29 78.47 180 bottom
Q5401  -  [TX_SC70_S6_H47]  74.47 76.12 90 bottom
Q7001  -  [TX_SOT23_2D4_H44]  32.02 48.35 270 bottom
Q7003  -  [TX_SC70_S6_H47]  35.85 48.09 0 bottom
Q7104  -  [TX_SOT23_2D4_H44]  58.03 15.3 0 bottom
Q7111  -  [TX_SOT23_2D4_H44]  67.39 26.59 180 bottom
Q7142  -  [TX_SC70_S6_H47]  85.85 16.04 90 bottom
Q7187  -  [TX_SC70_S6_H47]  63.25 14.92 180 bottom
Q7198  -  [TX_SC70_S6_H47]  62.83 18.63 180 bottom
Q7199  -  [TX_SC70_S6_H47]  79.11 16.85 180 bottom
Q8100  -  [TX_SC70_S6_H47]  71.6 43.67 0 bottom
Q8101  -  [TX_SC70_S6_H47]  41.78 48.93 180 bottom
Q8102  -  [TX_SC70_S6_H47]  42.47 51.85 270 bottom
Q8202  -  [TX_SOT23_2D4_H44]  50.21 17.29 270 bottom
Q8203  -  [TX_SC70_S6_H47]  52.65 21.5 270 bottom
Q8301  -  [TX_DFN_6P_26_79X79_2PAD_IR]  76.22 26.2 180 bottom
Q8302  -  [TX_DFN_6P_26_79X79_2PAD_IR]  78.51 25.99 0 bottom
Q8303  -  [TX_SOT23_2D4_H44]  36.21 62.32 180 bottom
Q8402  -  [TX_SOT23_2D4_H44]  40.16 41.51 270 bottom
Q8405  -  [TX_SOT23_2D4_H44]  33.4 51.5 90 bottom
Q8406  -  [TX_SC70_S6_H47]  38.81 51.85 270 bottom
Q8804  -  [TX_DFN_6P_26_S79_2PAD_H31]  30.93 15.3 0 bottom
Q8805  -  [TX_SC70_S6_H47]  33.98 14.66 180 bottom
Q8900  -  [TX_SOT23_2D4_H44]  38.99 38.31 270 bottom
Q9000  -  [TX_SOT23_2D4_H44]  39.82 17.26 180 bottom
R0501  -  [TX_R0402]  59.04 19.57 90 bottom
R0502  -  [TX_R0402]  60.55 19.57 90 bottom
R0503  -  [TX_R0402]  44.69 46.48 270 bottom
R0504  -  [TX_R0402]  42.13 34.48 270 bottom
R0505  -  [TX_R0402]  44.78 44.59 90 bottom
R0506  -  [TX_R0201_H10]  44.3 36.33 0 bottom
R0507  -  [TX_R0402]  43.28 35.6 0 bottom
R0508  -  [TX_R0402]  59.06 18.04 90 bottom
R0509  -  [TX_R0402]  60.55 18.05 90 bottom
R0510  -  [TX_R0402]  59.82 18.04 90 bottom
R0511  -  [TX_R0402]  45.42 46.48 90 bottom
R0512  -  [TX_R0402]  41.4 36.03 270 bottom
R0513  -  [TX_R0402]  45.54 44.59 270 bottom
R0514  -  [TX_R0201_H10]  43.26 36.46 0 bottom
R0515  -  [TX_R0402]  42.13 36.03 270 bottom
R0700  -  [TX_R0402]  84.89 60.72 270 bottom
R0703  -  [TX_R0402]  84.87 62.24 90 bottom
R0704  -  [TX_R0402]  84.87 63.76 270 bottom
R0706  -  [TX_R0402]  84.91 65.29 270 bottom
R0724  -  [TX_R0402]  92.34 86.67 180 bottom
R0734  -  [TX_R0402]  92.33 87.49 180 bottom
R0737  -  [TX_R0402]  91.67 90.81 180 bottom
R0753  -  [TX_R0402]  88.47 63.41 0 bottom
R0755  -  [TX_R0402]  85.6 63.02 270 bottom
R0757  -  [TX_R0402]  87.66 59.52 0 bottom
R0900  -  [TX_R0402]  89.4 39.13 90 bottom
R0901  -  [TX_R0402]  89.4 37.56 270 bottom
R0902  -  [TX_R0402]  89.4 42.17 90 bottom
R0903  -  [TX_R0402]  89.4 40.65 270 bottom
R0904  -  [TX_R0402]  89.4 48.27 90 bottom
R0905  -  [TX_R0402]  89.4 46.75 270 bottom
R0906  -  [TX_R0402]  89.4 45.22 90 bottom
R0907  -  [TX_R0402]  89.4 43.7 270 bottom
R0908  -  [TX_R0402]  85.08 29.8 270 bottom
R0909  -  [TX_R0402]  87.37 34.86 270 bottom
R0910  -  [TX_R0402]  87.37 33.33 270 bottom
R0911  -  [TX_R0402]  86.56 29.8 90 bottom
R0912  -  [TX_R0402]  88.13 30.34 90 bottom
R0913  -  [TX_R0402]  85.39 32.83 0 bottom
R0914  -  [TX_R0402_0OHM]  85.82 29.8 90 bottom
R1006  -  [TX_R0402]  29.66 58.53 180 bottom
R1007  -  [TX_R0402]  21.74 70.95 270 bottom
R1008  -  [TX_R0402]  20.95 70.95 270 bottom
R1009  -  [TX_R0402]  20.66 67.02 90 bottom
R1010  -  [TX_R0402]  35.43 68.92 270 bottom
R1014  -  [TX_R0402]  33.78 62.34 180 bottom
R1015  -  [TX_R0402]  33.78 63.08 180 bottom
R1017  -  [TX_R0402]  29.66 59.29 180 bottom
R1020  -  [TX_R0402]  26.9 72.17 90 bottom
R1026  -  [TX_R0402]  35.11 66.99 0 bottom
R1027  -  [TX_R0402]  35.11 67.75 0 bottom
R1034  -  [TX_R0402]  29.34 72.17 90 bottom
R1035  -  [TX_R0402]  28.58 72.17 90 bottom
R1036  -  [TX_R0402]  26.14 72.17 90 bottom
R1037  -  [TX_R0603_H24]  32.32 59.97 90 bottom
R1038  -  [TX_R0402]  34.74 65.46 90 bottom
R1045  -  [TX_R0402]  33.78 63.84 180 bottom
R1046  -  [TX_R0402]  20.66 65.52 270 bottom
R1047  -  [TX_R0402]  21.74 66.33 270 bottom
R1048  -  [TX_R0402]  20.69 68.54 90 bottom
R1050  -  [TX_R0402]  31.62 72.17 90 bottom
R1051  -  [TX_R0402]  30.85 70.57 90 bottom
R1052  -  [TX_R0402]  34.66 70.57 90 bottom
R1053  -  [TX_R0402]  33.14 70.57 90 bottom
R1101  -  [TX_R0402]  21.7 60.52 180 bottom
R1112  -  [TX_R0402]  33.62 6.82 270 bottom
R1113  -  [TX_R0402]  32.86 6.82 270 bottom
R1116  -  [TX_R0402]  26.23 58.91 270 bottom
R1117  -  [TX_R0402]  26.99 58.91 270 bottom
R1118  -  [TX_R0402]  26.31 60.89 90 bottom
R1119  -  [TX_R0402]  22.96 59.63 180 bottom
R1120  -  [TX_R0402]  36.73 6.82 270 bottom
R1121  -  [TX_R0402]  35.99 6.82 270 bottom
R1124  -  [TX_R0402]  89.31 106.97 270 bottom
R1125  -  [TX_R0402]  23.21 60.39 0 bottom
R1126  -  [TX_R0402]  21.7 61.24 180 bottom
R1127  -  [TX_R0402]  89.31 105.45 90 bottom
R1601  -  [TX_R0201_H10]  68.91 93.38 0 top
R1602  -  [TX_R0402]  60.59 101.53 90 bottom
R1603  -  [TX_R0402]  61.35 101.53 90 bottom
R1604  -  [TX_R0402]  70.09 101.53 90 bottom
R1605  -  [TX_R0402]  70.82 101.53 90 bottom
R1610  -  [TX_R0402]  57.82 97.32 180 bottom
R1611  -  [TX_R0402]  57.82 98.89 0 bottom
R1612  -  [TX_R0402]  58.38 101.53 90 bottom
R1613  -  [TX_R0402]  59.85 101.53 270 bottom
R1614  -  [TX_R0201_H10]  65.48 96 0 top
R1615  -  [TX_R0402]  68.63 101.53 90 bottom
R1616  -  [TX_R0402]  67.89 101.53 90 bottom
R1617  -  [TX_R0402]  64.97 101.53 90 bottom
R1618  -  [TX_R0402]  64.26 101.53 90 bottom
R1619  -  [TX_R0402]  62.08 101.53 90 bottom
R1620  -  [TX_R0402]  66.45 101.53 90 bottom
R1621  -  [TX_R0402]  62.81 101.53 90 bottom
R1622  -  [TX_R0402]  65.71 101.53 90 bottom
R1623  -  [TX_R0402]  63.55 101.53 90 bottom
R1624  -  [TX_R0402]  67.18 101.53 90 bottom
R1625  -  [TX_R0603_H24]  39.63 101.71 270 bottom
R1630  -  [TX_R0402]  67.12 86.85 180 bottom
R1701  -  [TX_R0402]  42.09 101.58 270 bottom
R1702  -  [TX_R0402]  42.81 101.58 90 bottom
R1703  -  [TX_R0402]  55.35 101.58 270 bottom
R1704  -  [TX_R0402]  56.12 101.58 90 bottom
R1709  -  [TX_R0402]  44.26 101.58 90 bottom
R1710  -  [TX_R0402]  44.99 101.58 90 bottom
R1711  -  [TX_R0402]  53.14 101.58 90 bottom
R1712  -  [TX_R0402]  53.87 101.58 90 bottom
R1713  -  [TX_R0402]  50.93 101.58 90 bottom
R1714  -  [TX_R0402]  52.4 101.58 90 bottom
R1715  -  [TX_R0402]  46.44 101.58 90 bottom
R1716  -  [TX_R0402]  51.66 101.58 90 bottom
R1717  -  [TX_R0402]  47.2 101.58 90 bottom
R1718  -  [TX_R0402]  50.17 101.58 90 bottom
R1719  -  [TX_R0402]  47.94 101.58 90 bottom
R1720  -  [TX_R0402]  48.68 101.58 90 bottom
R1721  -  [TX_R0402]  45.73 101.58 90 bottom
R1722  -  [TX_R0402]  49.44 101.58 90 bottom
R1724  -  [TX_R0201_H10]  47.91 96.12 180 top
R1725  -  [TX_R0201_H10]  51.59 93.33 180 top
R1730  -  [TX_R0402]  47.32 86.4 90 bottom
R1901  -  [TX_R0402]  33.55 82.72 270 bottom
R1902  -  [TX_R0402]  30.2 82.72 90 bottom
R1908  -  [TX_R0402]  28.68 82.72 90 bottom
R2008  -  [TX_R0402]  8.59 60.41 270 bottom
R2009  -  [TX_R0402]  8.59 61.93 90 bottom
R2010  -  [TX_R0402]  9.32 60.41 90 bottom
R2011  -  [TX_R0402]  9.32 61.93 270 bottom
R2015  -  [TX_R0402_0OHM]  24.64 6.16 270 bottom
R2016  -  [TX_R0402_0OHM]  25.38 6.16 270 bottom
R2017  -  [TX_R0402_0OHM]  28.09 5.34 180 bottom
R2018  -  [TX_R0402_0OHM]  28.09 4.61 180 bottom
R2020  -  [TX_R0402]  95.83 93.53 0 bottom
R2021  -  [TX_R0402]  95.83 94.29 0 bottom
R2030  -  [TX_R0402]  2.59 71.18 90 bottom
R2031  -  [TX_R0402]  3.35 71.18 90 bottom
R2040  -  [TX_R0402_0OHM]  26.75 6.18 180 bottom
R2064  -  [TX_R0402_0OHM]  25.88 2.68 180 bottom
R2088  -  [TX_R0402]  24.76 2.24 270 bottom
R2096  -  [TX_R0402]  26.9 3.92 270 bottom
R2097  -  [TX_R0402_0OHM]  29.87 4.99 180 bottom
R2098  -  [TX_R0402]  39.27 3.95 180 bottom
R2099  -  [TX_R0402]  39.27 7.07 180 bottom
R2101  -  [TX_R0402]  13.63 109.74 90 bottom
R2102  -  [TX_R0402]  11.35 109.74 90 bottom
R2103  -  [TX_R0402]  12.11 109.74 90 bottom
R2104  -  [TX_R0402]  15.34 112.38 180 bottom
R2121  -  [TX_R0402]  12.87 109.74 90 bottom
R2123  -  [TX_R0402]  15.41 110.13 180 bottom
R2129  -  [TX_R0402]  81.2 96.47 90 bottom
R2130  -  [TX_R0402]  80.44 98.02 90 bottom
R2131  -  [TX_R0402]  74.35 97.24 180 bottom
R2132  -  [TX_R0402]  15.41 109.41 180 bottom
R2134  -  [TX_R0402]  74.35 96.48 0 bottom
R2137  -  [TX_R0402]  11.73 107.1 180 bottom
R2138  -  [TX_R0402]  11.73 107.83 180 bottom
R2179  -  [TX_R0402]  15.42 108.65 0 bottom
R2301  -  [R0402]  84.35 4.96 0 bottom
R2400  -  [TX_R0402]  54.33 81.34 90 bottom
R2401  -  [TX_R0402]  52.86 81.34 270 bottom
R2402  -  [TX_R0402]  73.23 79.99 90 bottom
R2403  -  [TX_R0402]  73.97 79.99 90 bottom
R2404  -  [TX_R0402]  65.63 71.69 270 bottom
R2405  -  [TX_R0402]  64.87 73.21 270 bottom
R2406  -  [TX_R0402]  66.4 71.7 90 bottom
R2407  -  [TX_R0402]  73.46 87.41 90 bottom
R2408  -  [TX_R0402]  74.22 87.41 90 bottom
R2409  -  [TX_R0402]  41.58 62.39 0 bottom
R2410  -  [TX_R0402]  41.53 63.99 0 bottom
R2411  -  [TX_R0402]  43.13 62.39 180 bottom
R2506  -  [TX_R0402]  40.52 70.23 0 bottom
R2507  -  [TX_R0402]  40.05 66.88 90 bottom
R2508  -  [TX_R0402]  64.87 71.69 270 bottom
R2509  -  [TX_R0402]  40.78 67.58 270 bottom
R2510  -  [TX_R0402]  55.32 58.76 180 bottom
R2511  -  [TX_R0402]  53.8 58.76 0 bottom
R2512  -  [TX_R0402_SHORT_12MIL]  41.53 65.47 180 bottom
R2515  -  [TX_R0402]  80.29 65.21 90 bottom
R2516  -  [TX_R0402]  57.13 13.01 0 bottom
R2517  -  [TX_R0402]  64.11 73.21 90 bottom
R2518  -  [TX_R0402]  60.73 16.44 90 bottom
R2521  -  [TX_R0402]  73.61 78.52 180 bottom
R2522  -  [TX_R0402]  73.61 77.78 180 bottom
R2540  -  [TX_R0402]  17.15 84.31 180 bottom
R2542  -  [TX_R0402]  41.53 63.23 0 bottom
R2550  -  [TX_R0402]  30.85 72.17 90 bottom
R2600  -  [TX_R0402]  43.38 60.35 180 bottom
R2601  -  [TX_R0201_H10]  61.04 58.66 90 bottom
R2603  -  [TX_R0402]  67.69 58.63 0 bottom
R2604  -  [TX_R0201_H10]  77.65 74.66 0 bottom
R2608  -  [TX_R0402]  66.18 58.63 180 bottom
R2612  -  [TX_R0402]  64.68 58.63 0 bottom
R2613  -  [TX_R0402]  63.12 58.63 0 bottom
R2614  -  [TX_R0402]  65.28 63.69 0 bottom
R2615  -  [TX_R0201_H10]  70.08 61.48 180 bottom
R2617  -  [TX_R0402]  66.42 61.78 90 bottom
R2622  -  [TX_R0402]  56.85 58.85 0 bottom
R2623  -  [TX_R0402]  43.1 66.19 180 bottom
R2626  -  [TX_R0402]  78.87 65.06 180 bottom
R2627  -  [TX_R0402]  78.87 64.32 180 bottom
R2629  -  [TX_R0402]  67.2 69.54 270 bottom
R2630  -  [TX_R0402]  67.16 61.96 270 bottom
R2631  -  [TX_R0402]  58.4 58.4 0 bottom
R2632  -  [TX_R0402]  60 58.4 0 bottom
R2633  -  [TX_R0402]  63.34 61.79 90 bottom
R2634  -  [TX_R0402]  66.42 64.83 270 bottom
R2635  -  [TX_R0402]  61.6 59.57 0 bottom
R2636  -  [TX_R0402]  66.42 63.31 270 bottom
R2637  -  [TX_R0402]  41.45 66.2 180 bottom
R2638  -  [TX_R0201_H10]  62.08 58.66 270 bottom
R2640  -  [TX_R0201_H10]  65.02 67.57 180 bottom
R2641  -  [TX_R0201_H10]  76.91 79.28 90 bottom
R2642  -  [TX_R0201_H10]  66.52 70.69 0 bottom
R2643  -  [TX_R0201_0OHM_H10]  67.03 72.53 270 bottom
R2645  -  [TX_R0402]  65.25 68.26 180 bottom
R2649  -  [TX_R0402]  65.28 64.45 180 bottom
R2650  -  [TX_R0402]  32.21 9.08 90 bottom
R2651  -  [TX_R0402]  36.63 9.08 270 bottom
R2658  -  [TX_R0402]  65.28 65.21 180 bottom
R2659  -  [TX_R0201_H10]  67.08 71.46 90 bottom
R2667  -  [TX_R0402]  42.44 71.36 0 bottom
R2668  -  [TX_R0402]  42.44 72.09 0 bottom
R2676  -  [TX_R0402]  66.36 69.35 90 bottom
R2677  -  [TX_R0402]  38.6 66.05 180 bottom
R2678  -  [TX_R0201_H10]  58.4 59.32 270 bottom
R2683  -  [TX_R0402]  89.38 64.69 90 bottom
R2685  -  [TX_R0402]  66.4 73.21 90 bottom
R2687  -  [TX_R0201_H10]  57.86 59.32 270 bottom
R2688  -  [TX_R0201_H10]  66.07 67.57 0 bottom
R2690  -  [TX_R0201_H10]  23.95 74.03 180 bottom
R2691  -  [TX_R0402]  67.04 67 270 bottom
R2692  -  [TX_R0201_H10]  38.38 70.27 180 bottom
R2701  -  [TX_R0402]  80.72 73.72 90 bottom
R2702  -  [TX_R0402]  79.58 70.41 180 bottom
R2703  -  [TX_R0402]  80.72 72.2 270 bottom
R2710  -  [TX_R0402]  46.03 59.83 90 bottom
R2714  -  [TX_R0402]  46.41 60.95 180 bottom
R2715  -  [TX_R0402]  46.76 59.83 90 bottom
R2716  -  [TX_R0402]  47.52 59.93 270 bottom
R2720  -  [TX_R0402]  80.29 66.77 90 bottom
R2721  -  [TX_R0402]  43.56 71.74 90 bottom
R2722  -  [TX_R0603_0OHM_H24]  80.14 68.92 90 bottom
R2723  -  [TX_R0402]  42.75 67.29 90 bottom
R2724  -  [TX_R0603_0OHM_H24]  59.72 59.32 0 bottom
R2801  -  [TX_R0603_H24]  45.75 81.11 0 bottom
R3001  -  [TX_R0402]  78.82 68.22 180 bottom
R3002  -  [TX_R0402]  68.3 61.55 0 bottom
R3015  -  [TX_R0402]  78.82 69.68 0 bottom
R3036  -  [TX_R0402]  66.32 66.39 270 bottom
R3037  -  [TX_R0402]  67.18 65.06 90 bottom
R3042  -  [TX_R0402]  74.52 81.16 180 bottom
R3045  -  [TX_R0402]  75.82 62.85 180 bottom
R3046  -  [TX_R0402]  78.87 62.85 0 bottom
R3047  -  [TX_R0402]  77.34 62.85 180 bottom
R3056  -  [TX_R0402]  67.16 63.5 270 bottom
R3060  -  [TX_R0402]  72.2 62.85 0 bottom
R3061  -  [TX_R0402]  81.05 75.8 90 bottom
R3062  -  [TX_R0402]  75.85 74.66 0 bottom
R3066  -  [TX_R0402]  67.46 73.91 90 bottom
R3070  -  [TX_R0402]  75.34 58.79 0 bottom
R3077  -  [TX_R0402]  68.22 73.91 90 bottom
R3078  -  [TX_R0402]  74.91 99.93 0 bottom
R3079  -  [TX_R0402]  74.91 100.67 0 bottom
R3080  -  [TX_R0402]  73.76 58.78 0 bottom
R3081  -  [TX_R0402]  76.91 60.13 90 bottom
R3082  -  [TX_R0402]  73.31 61.99 0 bottom
R3083  -  [TX_R0402]  68.02 60.39 90 bottom
R3084  -  [TX_R0402]  71.48 61.58 0 bottom
R3101  -  [TX_R0402]  36.83 97.85 180 bottom
R3315  -  [TX_R0201_0OHM_H10]  14.37 74.64 0 bottom
R3338  -  [TX_R0402]  80.65 91.88 90 bottom
R3339  -  [TX_R0402]  72.77 90.36 90 bottom
R3340  -  [TX_R0402]  72.77 92.9 90 bottom
R3341  -  [TX_R0402]  80.65 93.41 90 bottom
R3342  -  [TX_R0201_H10]  76.54 85.13 180 bottom
R3343  -  [TX_R0402]  77.19 80.78 270 bottom
R3344  -  [TX_R0402]  78.66 80.78 90 bottom
R3345  -  [TX_R0201_0OHM_H10]  80.65 94.68 90 bottom
R3346  -  [TX_R0201_0OHM_H10]  72.77 91.63 90 bottom
R3347  -  [TX_R0201_0OHM_H10]  73.66 89.82 180 bottom
R3348  -  [TX_R0402]  77.93 80.78 90 bottom
R3350  -  [TX_R0201_H10]  75.48 85.13 180 bottom
R3351  -  [TX_R0402]  76.05 81.19 180 bottom
R3352  -  [TX_R0402]  80.16 80.78 270 bottom
R3803  -  [TX_R0402]  84.4 98.71 90 bottom
R3810  -  [TX_R0201_0OHM_H10]  84.46 92.69 0 bottom
R5101  -  [TX_R0402]  31.06 8.7 180 bottom
R5105  -  [TX_R0402]  27.86 7.73 90 bottom
R5106  -  [TX_R0402]  27.86 9.26 270 bottom
R5107  -  [TX_R0402]  25.15 7.27 0 bottom
R5110  -  [TX_R0402]  29.92 4.25 180 bottom
R5201  -  [TX_R0402]  72.28 53.53 0 bottom
R5204  -  [TX_R0402]  78.15 52.82 90 bottom
R5205  -  [TX_R0402]  77.41 52.82 90 bottom
R5401  -  [TX_R0402]  2.72 81.01 270 bottom
R5402  -  [TX_R0402]  2.62 79.44 90 bottom
R5403  -  [TX_R0402]  2.72 77.89 90 bottom
R5404  -  [TX_R0402]  2.72 76.31 90 bottom
R5405  -  [TX_R0402]  3.46 74.25 90 bottom
R5406  -  [TX_R0402]  4.22 74.25 90 bottom
R5407  -  [TX_R0402]  17.15 82.81 180 bottom
R5408  -  [TX_R0402]  17.15 82.05 180 bottom
R5409  -  [TX_R0402]  17.15 80.53 180 bottom
R5410  -  [TX_R0402]  17.15 81.29 180 bottom
R5411  -  [TX_R0402]  17.15 85.81 180 bottom
R5412  -  [TX_R0402]  17.15 86.57 180 bottom
R5413  -  [TX_R0402]  17.15 83.58 180 bottom
R5414  -  [TX_R0402]  17.15 85.05 180 bottom
R5415  -  [TX_R0402]  1.87 82.54 270 bottom
R5416  -  [TX_R0402]  2.71 82.54 270 bottom
R5417  -  [TX_R0402]  17.15 79 180 bottom
R5418  -  [TX_R0402]  2.72 85.86 270 bottom
R5420  -  [TX_R0402]  2.34 84.74 180 bottom
R5421  -  [TX_R0402]  5.03 72.7 90 bottom
R5422  -  [TX_R0402]  17.15 78.24 180 bottom
R5423  -  [TX_R0402]  5.03 74.25 90 bottom
R5424  -  [TX_R0402]  2.36 88.88 0 bottom
R5425  -  [TX_R0402]  17.15 79.77 180 bottom
R5426  -  [TX_R0402]  7.26 74.26 90 bottom
R5427  -  [TX_R0402]  8.71 73.09 180 bottom
R5428  -  [TX_R0402]  6.53 74.26 90 bottom
R5429  -  [TX_R0402]  1.88 79.44 270 bottom
R5430  -  [TX_R0402]  1.88 77.89 270 bottom
R5431  -  [TX_R0402]  1.88 76.31 270 bottom
R5432  -  [TX_R0402]  2.31 75.09 0 bottom
R5433  -  [TX_R0402]  4.22 72.73 90 bottom
R5818  -  [TX_R0402]  66.09 112.48 90 bottom
R5819  -  [TX_R0402]  66.85 112.48 90 bottom
R5820  -  [TX_R0402]  65.35 112.48 90 bottom
R5821  -  [TX_R0402]  67.59 112.48 90 bottom
R5822  -  [TX_R0402]  71.74 115.37 180 bottom
R5824  -  [TX_R0402]  68.4 114 180 bottom
R5825  -  [TX_R0402]  90.96 66.48 180 bottom
R5826  -  [TX_R0402]  90.96 67.24 180 bottom
R5831  -  [TX_R0402]  87.83 110.91 270 bottom
R5833  -  [TX_R0402]  92.51 65.01 180 bottom
R5842  -  [TX_R0402]  34.8 99.55 180 bottom
R5847  -  [TX_R0402]  34.8 100.29 0 bottom
R5848  -  [TX_R0402]  28.68 98.62 0 bottom
R5849  -  [TX_R0402]  28.65 100.64 180 bottom
R5860  -  [TX_R0402]  27.14 97.87 0 bottom
R5861  -  [TX_R0402]  89.31 110.04 90 bottom
R5866  -  [TX_R0402]  34.8 98.05 0 bottom
R5867  -  [TX_R0402]  34.8 98.79 0 bottom
R5870  -  [TX_R0402]  71.74 116.11 0 bottom
R5871  -  [TX_R0402]  92.51 66.48 0 bottom
R5899  -  [TX_R0402]  88.57 110.04 90 bottom
R7001  -  [TX_R0402]  37.71 48.75 0 bottom
R7002  -  [TX_R0402]  37.71 49.49 0 bottom
R7004  -  [TX_R0402]  34.37 47.56 90 bottom
R7005  -  [TX_R0402]  30.35 50.71 270 bottom
R7006  -  [TX_R0402]  38.13 47.63 270 bottom
R7007  -  [TX_R0402]  39.22 46.85 270 bottom
R7102  -  [TX_R0402]  75.56 14.82 180 bottom
R7103  -  [TX_R0402]  72.18 23.71 180 bottom
R7104  -  [TX_R0402]  75.56 15.58 0 bottom
R7105  -  [TX_R0402]  75.56 16.34 0 bottom
R7106  -  [TX_R0402]  70.66 23.71 180 bottom
R7107  -  [TX_R0402]  76.78 17.23 180 bottom
R7108  -  [TX_R0402]  70.66 22.95 0 bottom
R7109  -  [TX_R0402]  74.67 18.12 180 bottom
R7110  -  [TX_R0402]  76.78 18.12 180 bottom
R7113  -  [TX_R0402]  78.73 19.14 0 bottom
R7114  -  [TX_R0402]  78.89 20.28 0 bottom
R7115  -  [TX_R0402]  75.56 14.06 180 bottom
R7116  -  [TX_R0402]  75.56 13.14 180 bottom
R7119  -  [TX_R0402]  74.67 17.23 180 bottom
R7122  -  [TX_R0402]  64.97 21.7 270 bottom
R7127  -  [TX_R0402]  61.29 19.57 90 bottom
R7129  -  [TX_R0402]  65.2 18.47 270 bottom
R7132  -  [TX_R0402]  84.46 14.11 90 bottom
R7135  -  [TX_R0402]  76.81 34.12 270 bottom
R7136  -  [TX_R0402]  76.07 34.12 270 bottom
R7137  -  [TX_R0402]  55.65 15.17 180 bottom
R7138  -  [TX_R0402]  55.65 14.41 180 bottom
R7139  -  [TX_R0402]  54.07 14.41 0 bottom
R7141  -  [TX_R0402]  52.5 15.17 180 bottom
R7142  -  [TX_R0402]  66.47 23.75 90 bottom
R7143  -  [TX_R0402]  65.75 22.15 90 bottom
R7144  -  [TX_R0402]  78.39 14.61 180 bottom
R7145  -  [TX_R0402]  73.65 13.14 180 bottom
R7147  -  [TX_R0402]  54.07 15.17 0 bottom
R7151  -  [TX_R0402]  65.17 13.9 180 bottom
R7152  -  [TX_R0402]  65.17 15.43 0 bottom
R7153  -  [TX_R0402]  60.42 13.79 0 bottom
R7154  -  [TX_R0402]  41.17 25.21 180 bottom
R7156  -  [TX_R0402]  60.42 15.29 0 bottom
R7158  -  [TX_R0402]  60.17 13.01 180 bottom
